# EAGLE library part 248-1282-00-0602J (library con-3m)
Zero Insertion Force Socked Source: http://www.3M.com/ehpd
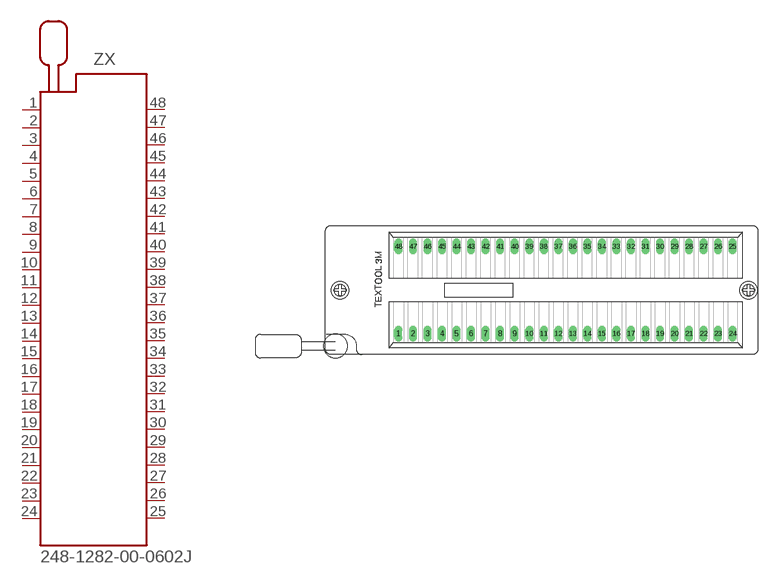
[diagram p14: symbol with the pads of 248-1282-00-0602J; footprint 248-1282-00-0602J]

Designator prefix ZX

## 248-1282-00-0602J (MF: 3M; MPN: 248-1282-00-0602J; OC_FARNELL: 9897488; OC_NEWARK: 85K7866)  [248-1282-00-0602J]
1  1  pas
2  2  pas
3  3  pas
4  4  pas
5  5  pas
6  6  pas
7  7  pas
8  8  pas
9  9  pas
10  10  pas
11  11  pas
12  12  pas
13  13  pas
14  14  pas
15  15  pas
16  16  pas
17  17  pas
18  18  pas
19  19  pas
20  20  pas
21  21  pas
22  22  pas
23  23  pas
24  24  pas
25  25  pas
26  26  pas
27  27  pas
28  28  pas
29  29  pas
30  30  pas
31  31  pas
32  32  pas
33  33  pas
34  34  pas
35  35  pas
36  36  pas
37  37  pas
38  38  pas
39  39  pas
40  40  pas
41  41  pas
42  42  pas
43  43  pas
44  44  pas
45  45  pas
46  46  pas
47  47  pas
48  48  pas

## Footprint 248-1282-00-0602J (pad centres in mm)
3M TEXTOOL 48 pol. DIP Lever actuated zero insertion force mechanism Hersteller: 3M TEXTOOL Herstellerbez.: 248-1282-00-0602J Source: http://www.3M.com/ehpd
drill 0.9 long: 1 -29.21,-7.62; 2 -26.67,-7.62; 3 -24.13,-7.62; 4 -21.59,-7.62; 5 -19.05,-7.62; 6 -16.51,-7.62; 7 -13.97,-7.62; 8 -11.43,-7.62; 9 -8.89,-7.62; 10 -6.35,-7.62; 11 -3.81,-7.62; 12 -1.27,-7.62; 13 1.27,-7.62; 14 3.81,-7.62; 15 6.35,-7.62; 16 8.89,-7.62; 17 11.43,-7.62; 18 13.97,-7.62; 19 16.51,-7.62; 20 19.05,-7.62; 21 21.59,-7.62; 22 24.13,-7.62; 23 26.67,-7.62; 24 29.21,-7.62; 25 29.21,7.62; 26 26.67,7.62; 27 24.13,7.62; 28 21.59,7.62; 29 19.05,7.62; 30 16.51,7.62; 31 13.97,7.62; 32 11.43,7.62; 33 8.89,7.62; 34 6.35,7.62; 35 3.81,7.62; 36 1.27,7.62; 37 -1.27,7.62; 38 -3.81,7.62; 39 -6.35,7.62; 40 -8.89,7.62; 41 -11.43,7.62; 42 -13.97,7.62; 43 -16.51,7.62; 44 -19.05,7.62; 45 -21.59,7.62; 46 -24.13,7.62; 47 -26.67,7.62; 48 -29.21,7.62
hole 2 at -39.4,0
hole 2 at 32,0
